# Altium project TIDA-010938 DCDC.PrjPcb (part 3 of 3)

## Sheet TIDA-010938 bidirectional DC-DC_Interleaved2.SchDoc
size 558 x 431 mm; SheetNumber: 8; SheetTotal: 9
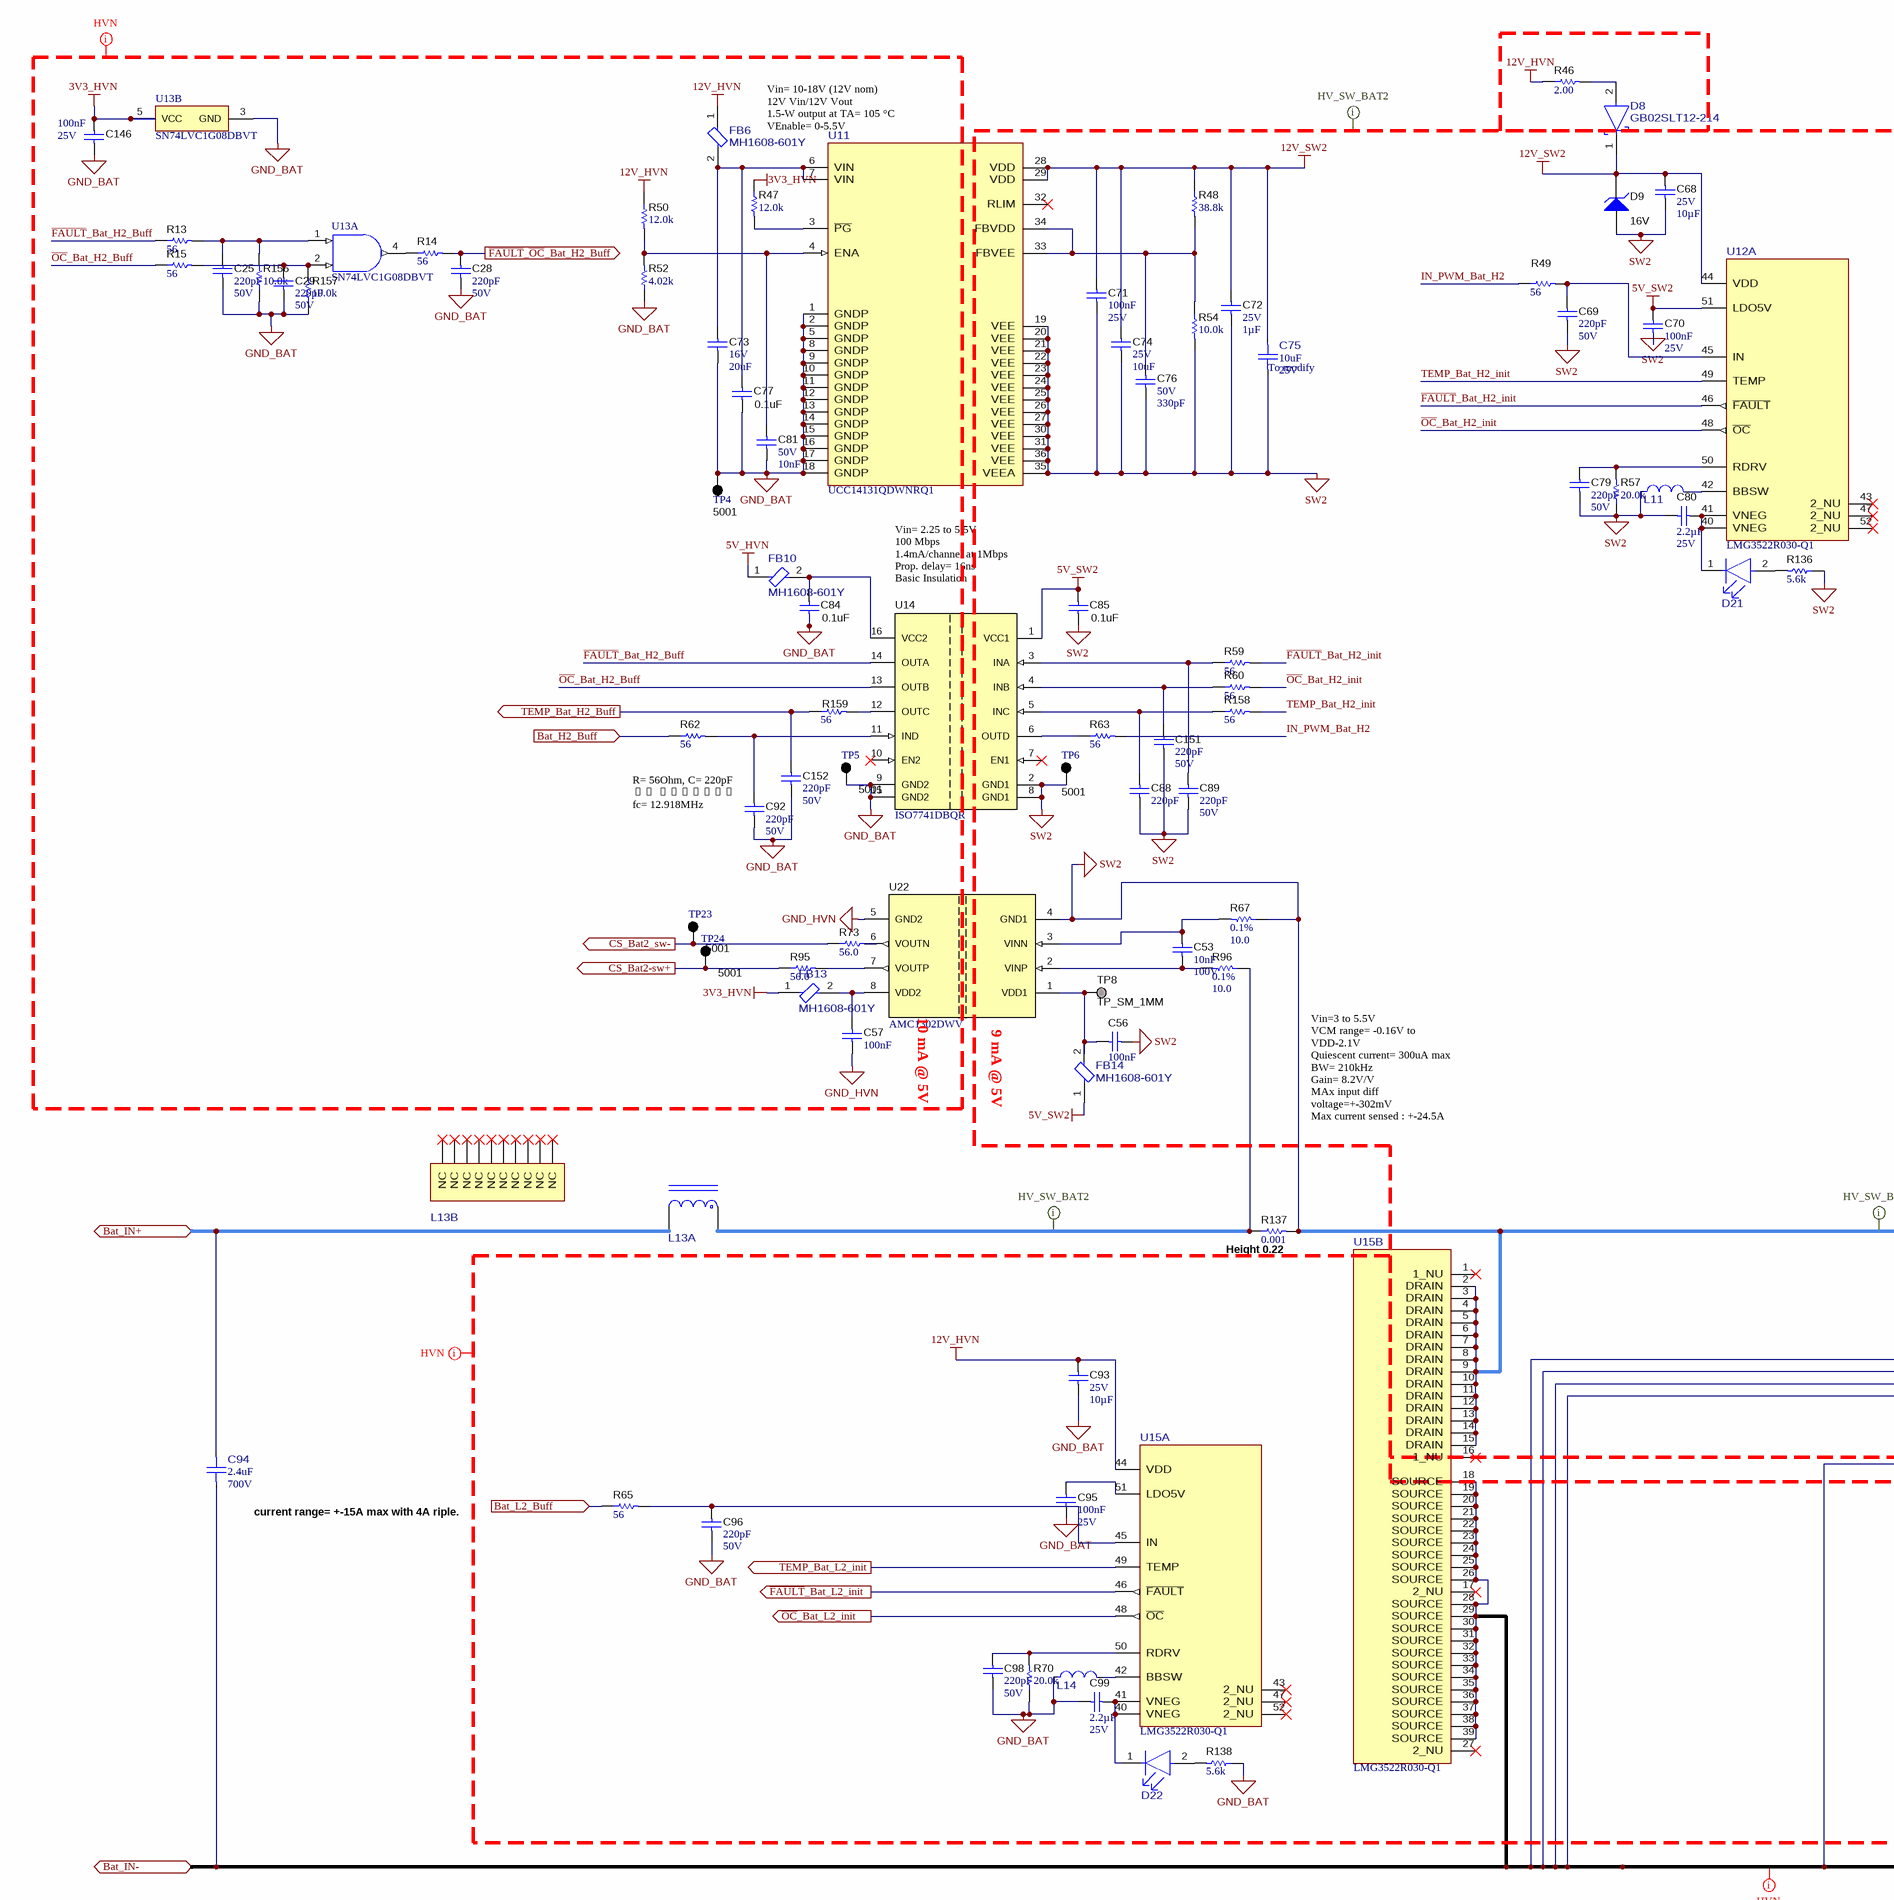
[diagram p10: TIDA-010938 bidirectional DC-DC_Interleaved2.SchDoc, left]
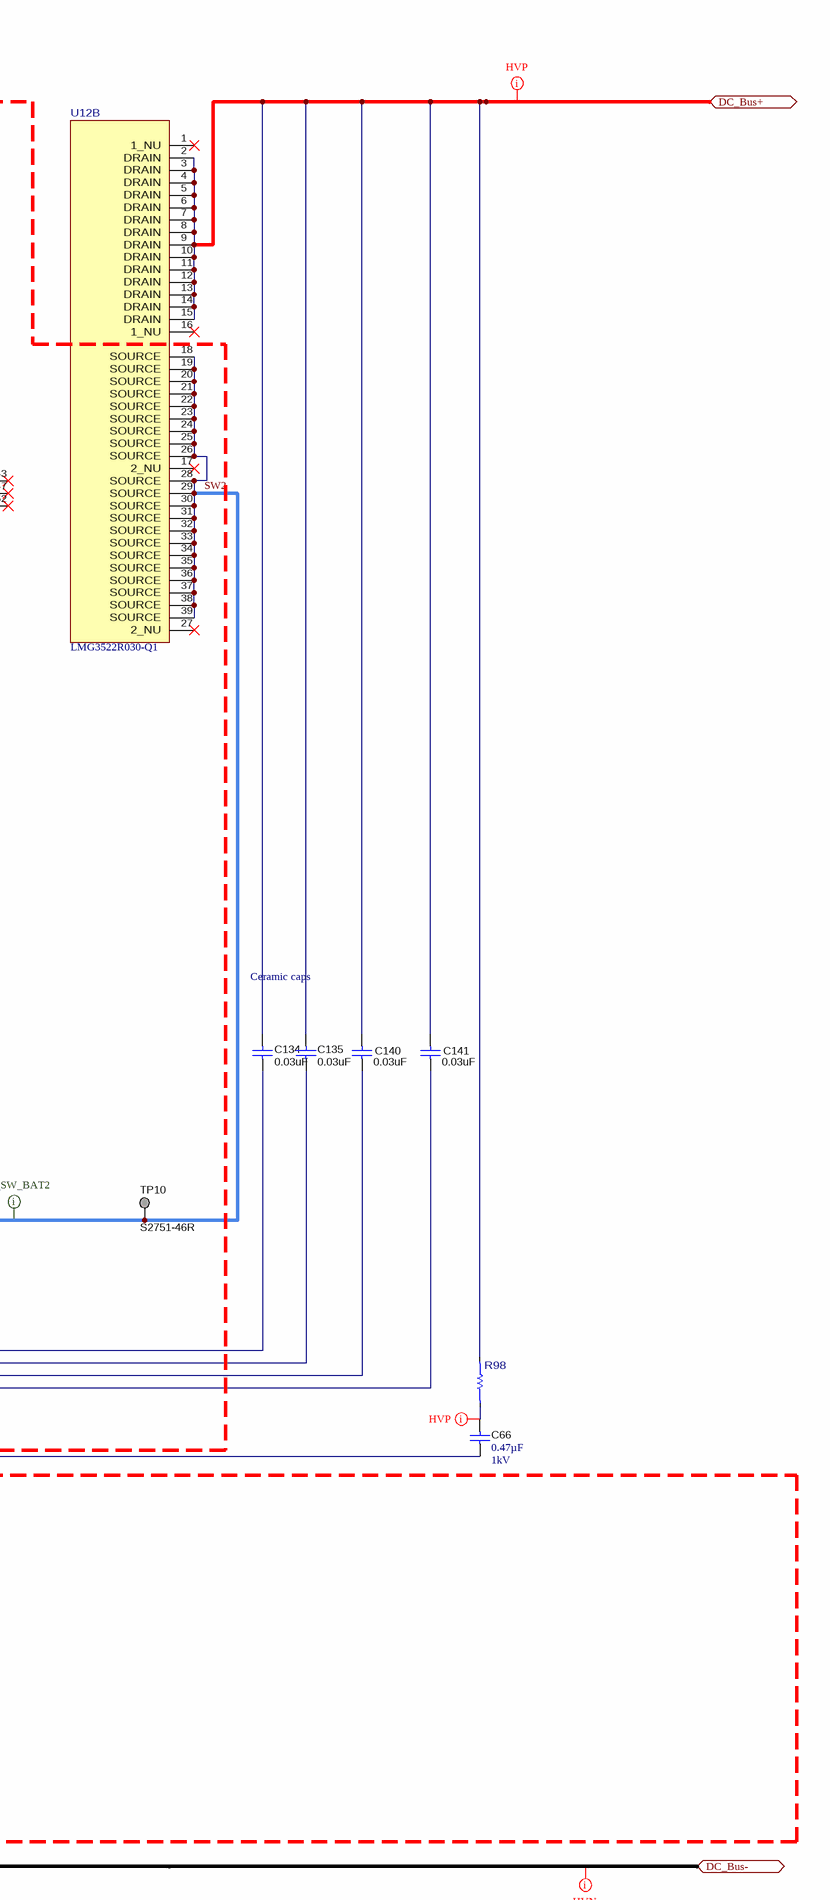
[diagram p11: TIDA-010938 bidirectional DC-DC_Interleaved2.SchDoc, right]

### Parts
C25  Cap_F: 220pF  VDC_V: 50V  [0603]  (hidden comment: GRM188R71H221KA01D)
C28  Cap_F: 220pF  VDC_V: 50V  [0603]  (hidden comment: GRM188R71H221KA01D)
C29  Cap_F: 220pF  VDC_V: 50V  [0603]  (hidden comment: GRM188R71H221KA01D)
C53  Cap_F: 10nF  VDC_V: 100V  [0603]  (hidden comment: CGA3E2X7R2A103K080AA)
C56  Cap_F: 100nF  [0603]  (hidden comment: 06033C104JAT2A)
C57  Cap_F: 100nF  [0603]  (hidden comment: 06033C104JAT2A)
C66  ValueDisplayed: 0.47µF  VDC_V: 1kV  [2220]  (hidden comment: 2220Y1K00474KETWS2)
C68  VDC_V: 25V  ValueDisplayed: 10µF  [1206_180]  (hidden comment: TMK316AB7106KLHT)
C69  Cap_F: 220pF  VDC_V: 50V  [0603]  (hidden comment: GRM188R71H221KA01D)
C70  Cap_F: 100nF  VDC_V: 25V  [0603]  (hidden comment: 06033C104JAT2A)
C71  Cap_F: 100nF  VDC_V: 25V  [0603]  (hidden comment: 06033C104JAT2A)
C72  VDC_V: 25V  ValueDisplayed: 1µF  [0603]  (hidden comment: TMK107BJ105KA-T)
C73  VDC_V: 16V  ValueDisplayed: 20uF  [0704]  (hidden comment: GRMJN7R61C206ME05)
C74  VDC_V: 25V  ValueDisplayed: 10uF  [0603]  (hidden comment: TMK107BBJ106MA-T)
C75  ValueDisplayed: 10uF  VDC_V: 25V  [FP-ZRB18AR61E106ME01L_0603-MFG]  (hidden comment: ZRB18AR61E106ME01L)
C76  VDC_V: 50V  ValueDisplayed: 330pF  [0603]  (hidden comment: GRM1885C1H331JA01D)
C77  ValueDisplayed: 0.1uF  [0603]  (hidden comment: 885012206095)
C79  Cap_F: 220pF  VDC_V: 50V  [0603]  (hidden comment: GRM188R71H221KA01D)
C80  Cap_F: 2.2µF  VDC_V: 25V  [0805_HV]  (hidden comment: CGA4J3X7R1E225K125AB)
C81  VDC_V: 50V  Cap_F: 10nF  [0603]  (hidden comment: 885012206089)
C84  ValueDisplayed: 0.1uF  [0603]  (hidden comment: 885012206095)
C85  ValueDisplayed: 0.1uF  [0603]  (hidden comment: 885012206095)
C88  Cap_F: 220pF  [0603]  (hidden comment: GRM188R71H221KA01D)
C89  Cap_F: 220pF  VDC_V: 50V  [0603]  (hidden comment: GRM188R71H221KA01D)
C92  Cap_F: 220pF  VDC_V: 50V  [0603]  (hidden comment: GRM188R71H221KA01D)
C93  VDC_V: 25V  ValueDisplayed: 10µF  [1206_180]  (hidden comment: TMK316AB7106KLHT)
C94  ValueDisplayed: 2.4uF  VDC_V: 700V  [FP-C4AUJBU4240M1WJ_RADIAL-MFG]  (hidden comment: C4AUJBU4240M1WJ)
C95  Cap_F: 100nF  VDC_V: 25V  [0603]  (hidden comment: 06033C104JAT2A)
C96  Cap_F: 220pF  VDC_V: 50V  [0603]  (hidden comment: GRM188R71H221KA01D)
C98  Cap_F: 220pF  VDC_V: 50V  [0603]  (hidden comment: GRM188R71H221KA01D)
C99  Cap_F: 2.2µF  VDC_V: 25V  [0805_HV]  (hidden comment: CGA4J3X7R1E225K125AB)
C134  ValueDisplayed: 0.03uF  [1812_254]  (hidden comment: C1812C303KDGLCAUTO)
C135  ValueDisplayed: 0.03uF  [1812_254]  (hidden comment: C1812C303KDGLCAUTO)
C140  ValueDisplayed: 0.03uF  [1812_254]  (hidden comment: C1812C303KDGLCAUTO)
C141  ValueDisplayed: 0.03uF  [1812_254]  (hidden comment: C1812C303KDGLCAUTO)
C146  Cap_F: 100nF  VDC_V: 25V  [0603]  (hidden comment: 06033C104JAT2A)
C151  Cap_F: 220pF  VDC_V: 50V  [0603]  (hidden comment: GRM188R71H221KA01D)
C152  Cap_F: 220pF  VDC_V: 50V  [0603]  (hidden comment: GRM188R71H221KA01D)
D8  GB02SLT12-214  [FP-GB02SLT12-214_DO-214AA-MFG]
D9  value 16V  [SOD-123]  (hidden comment: BZT52C16-7-F)
D21  KG DELLS1.22-JGKH-24  [FP-KG DELLS1.22-JGKH-24_0603-MFG]  (value not drawn)
D22  KG DELLS1.22-JGKH-24  [FP-KG DELLS1.22-JGKH-24_0603-MFG]  (value not drawn)
FB6  MH1608-601Y  [FP-MH1608-601Y_0603-MFG]
FB10  MH1608-601Y  [FP-MH1608-601Y_0603-MFG]
FB13  MH1608-601Y  [FP-MH1608-601Y_0603-MFG]
FB14  MH1608-601Y  [FP-MH1608-601Y_0603-MFG]
L11  SDEM20161T-4R7MS  [FP-SDEM20161T-4R7MS_SMD2-MFG]  (value not drawn)
L13  B180975  [FP-B180975_PTH12_55MM5_50MM0-MFG]  (value not drawn)  (parts A,B of 2)
L14  SDEM20161T-4R7MS  [FP-SDEM20161T-4R7MS_SMD2-MFG]  (value not drawn)
R13  ValueDisplayed: 56  [0603]  (hidden comment: RG1608P-560-B-T5)
R14  ValueDisplayed: 56  [0603]  (hidden comment: RG1608P-560-B-T5)
R15  ValueDisplayed: 56  [0603]  (hidden comment: RG1608P-560-B-T5)
R46  ValueDisplayed: 2.00  [0603]  (hidden comment: RT0603DRE072RL)
R47  ValueDisplayed: 12.0k  [0603]  (hidden comment: ERJ-3EKF1202V)
R48  ValueDisplayed: 38.8k  [0603]  (hidden comment: RT0603DRE0738K8L)
R49  ValueDisplayed: 56  [0603]  (hidden comment: RG1608P-560-B-T5)
R50  ValueDisplayed: 12.0k  [0603]  (hidden comment: ERJ-3EKF1202V)
R52  ValueDisplayed: 4.02k  [0603]  (hidden comment: RT0603BRD074K02L)
R54  ValueDisplayed: 10.0k  [0603]  (hidden comment: RG1608P-103-B-T5)
R57  ValueDisplayed: 20.0k  [0603]  (hidden comment: RC0603FR-0720KL)
R59  ValueDisplayed: 56  [0603]  (hidden comment: RG1608P-560-B-T5)
R60  ValueDisplayed: 56  [0603]  (hidden comment: RG1608P-560-B-T5)
R62  ValueDisplayed: 56  [0603]  (hidden comment: RG1608P-560-B-T5)
R63  ValueDisplayed: 56  [0603]  (hidden comment: RG1608P-560-B-T5)
R65  ValueDisplayed: 56  [0603]  (hidden comment: RG1608P-560-B-T5)
R67  Tolerance_%: 0.1%  ValueDisplayed: 10.0  [0603]  (hidden comment: RT0603BRD0710RL)
R70  ValueDisplayed: 20.0k  [0603]  (hidden comment: RC0603FR-0720KL)
R73  ValueDisplayed: 56.0  [0603]  (hidden comment: RC0603FR-0756RL)
R95  ValueDisplayed: 56.0  [0603]  (hidden comment: RC0603FR-0756RL)
R96  Tolerance_%: 0.1%  ValueDisplayed: 10.0  [0603]  (hidden comment: RT0603BRD0710RL)
R98  CSR0805FKR250  [FP-CSR0805FKR250_0805-MFG]  (value not drawn)
R136  ValueDisplayed: 5.6k  [0603]  (hidden comment: RC0603JR-075K6L)
R137  ValueDisplayed: 0.001  [CSS2H-2512_H077Y042]  (hidden comment: CSS2H-2512R-1L00F)
R138  ValueDisplayed: 5.6k  [0603]  (hidden comment: RC0603JR-075K6L)
R156  ValueDisplayed: 10.0k  [0603]  (hidden comment: RG1608P-103-B-T5)
R157  ValueDisplayed: 10.0k  [0603]  (hidden comment: RG1608P-103-B-T5)
R158  ValueDisplayed: 56  [0603]  (hidden comment: RG1608P-560-B-T5)
R159  ValueDisplayed: 56  [0603]  (hidden comment: RG1608P-560-B-T5)
TP4  5001  [Keystone5001]
TP5  5001  [Keystone5001]
TP6  5001  [Keystone5001]
TP8  TP_SM_1MM  [TP_SM_1MM]  (no BOM)
TP10  S2751-46R  [Harwin_S2751-46R]  (no BOM)
TP23  5001  [Keystone5001]
TP24  5001  [Keystone5001]
U11  UCC14131QDWNRQ1  [DWJ0036A-MFG]
U12  LMG3522R030-Q1  [RQS0052C-C01-MFG]  (parts A,B of 2)
U13  SN74LVC1G08DBVT  [DBV0005A_N]  (parts A,B of 2)
U14  ISO7741DBQR  [DBQ0016A_N]
U15  LMG3522R030-Q1  [RQS0052C-C01-MFG]  (parts A,B of 2)
U22  AMC1302DWV  [DWV0008A]

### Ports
Bat_H2_Buff (in), Bat_IN+ (bidir), Bat_IN- (bidir), Bat_L2_Buff (in), CS_Bat2-sw+ (out), CS_Bat2_sw- (out), DC_Bus+ (bidir), DC_Bus- (bidir), TEMP_Bat_H2_Buff (out), TEMP_Bat_L2_init (out), ~{FAULT}_Bat_L2_init (out), ~{FAULT}_~{OC}_Bat_H2_Buff (out), ~{OC}_Bat_L2_init (out)

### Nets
3V3_HVN: C146.1 FB13.1 R47.1 U13.5(VCC)
5V_HVN: FB10.1
5V_SW2: C70.2 C85.1 FB14.1 U12.51(LDO5V) U14.1(VCC1)
12V_HVN: C93.1 FB6.1 R46.1 R50.1 U15.44(VDD)
12V_SW2: C68.1 C71.2 C72.2 C74.2 C75.1 D8.1(CATHODE) D9.1(K) R48.1 U11.28(VDD) U11.29(VDD) U12.44(VDD)
DC_Bus-: C66.2 C94.1 C134.2 C135.2 C140.2 C141.2 U15.18(SOURCE) U15.19(SOURCE) U15.20(SOURCE) U15.21(SOURCE) U15.22(SOURCE) U15.23(SOURCE) U15.24(SOURCE) U15.25(SOURCE) U15.26(SOURCE) U15.28(SOURCE) U15.29(SOURCE) U15.30(SOURCE) U15.31(SOURCE) U15.32(SOURCE) U15.33(SOURCE) U15.34(SOURCE) U15.35(SOURCE) U15.36(SOURCE) U15.37(SOURCE) U15.38(SOURCE) U15.39(SOURCE) ; port DC_Bus-, port Bat_IN-
GND_BAT: C25.1 C28.1 C29.1 C73.1 C77.2 C81.1 C84.2 C92.1 C93.2 C95.1 C96.1 C98.1 C99.2 C146.2 C152.1 L14.1 R52.1 R70.1 R138.1 R156.1 R157.1 TP4.1 TP5.1 U11.1(GNDP) U11.2(GNDP) U11.5(GNDP) U11.8(GNDP) U11.9(GNDP) U11.10(GNDP) U11.11(GNDP) U11.12(GNDP) U11.13(GNDP) U11.14(GNDP) U11.15(GNDP) U11.16(GNDP) U11.17(GNDP) U11.18(GNDP) U13.3(GND) U14.9(GND2) U14.15(GND2)
GND_HVN: C57.2 U22.5(GND2)
SW2: C56.2 C68.2 C69.1 C70.1 C71.1 C72.1 C74.1 C75.2 C76.2 C79.1 C80.2 C85.2 C88.1 C89.1 C151.1 D9.2(A) L11.1 R54.2 R57.1 R67.1 R136.1 R137.2 TP6.1 TP10.1 U11.19(VEE) U11.20(VEE) U11.21(VEE) U11.22(VEE) U11.23(VEE) U11.24(VEE) U11.25(VEE) U11.26(VEE) U11.27(VEE) U11.30(VEE) U11.31(VEE) U11.35(VEEA) U11.36(VEE) U12.18(SOURCE) U12.19(SOURCE) U12.20(SOURCE) U12.21(SOURCE) U12.22(SOURCE) U12.23(SOURCE) U12.24(SOURCE) U12.25(SOURCE) U12.26(SOURCE) U12.28(SOURCE) U12.29(SOURCE) U12.30(SOURCE) U12.31(SOURCE) U12.32(SOURCE) U12.33(SOURCE) U12.34(SOURCE) U12.35(SOURCE) U12.36(SOURCE) U12.37(SOURCE) U12.38(SOURCE) U12.39(SOURCE) U14.2(GND1) U14.8(GND1) U15.2(DRAIN) U15.3(DRAIN) U15.4(DRAIN) U15.5(DRAIN) U15.6(DRAIN) U15.7(DRAIN) U15.8(DRAIN) U15.9(DRAIN) U15.10(DRAIN) U15.11(DRAIN) U15.12(DRAIN) U15.13(DRAIN) U15.14(DRAIN) U15.15(DRAIN) U22.4(GND1)
Bat_H2_Buff: R62.1 ; port Bat_H2_Buff
Bat_IN+: C94.2 L13.6 ; port Bat_IN+
Bat_L2_Buff: R65.1 ; port Bat_L2_Buff
CS_Bat2-sw+: R95.1 TP24.1 ; port CS_Bat2-sw+
CS_Bat2_sw-: R73.1 TP23.1 ; port CS_Bat2_sw-
DC_Bus+: C134.1 C135.1 C140.1 C141.1 R98.2 U12.2(DRAIN) U12.3(DRAIN) U12.4(DRAIN) U12.5(DRAIN) U12.6(DRAIN) U12.7(DRAIN) U12.8(DRAIN) U12.9(DRAIN) U12.10(DRAIN) U12.11(DRAIN) U12.12(DRAIN) U12.13(DRAIN) U12.14(DRAIN) U12.15(DRAIN) ; port DC_Bus+
~{FAULT}_Bat_H2_Buff: R13.1 U14.14(OUTA)
~{FAULT}_Bat_H2_init: R59.2 U12.46(~{FAULT})
~{FAULT}_Bat_L2_init: U15.46(~{FAULT}) ; port ~{FAULT}_Bat_L2_init
~{FAULT}_~{OC}_Bat_H2_Buff: C28.2 R14.2 ; port ~{FAULT}_~{OC}_Bat_H2_Buff
IN_PWM_Bat_H2: R49.1 R63.2
~{OC}_Bat_H2_Buff: R15.1 U14.13(OUTB)
~{OC}_Bat_H2_init: R60.2 U12.48(~{OC})
~{OC}_Bat_L2_init: U15.48(~{OC}) ; port ~{OC}_Bat_L2_init
TEMP_Bat_H2_Buff: C152.2 R159.1 ; port TEMP_Bat_H2_Buff
TEMP_Bat_H2_init: R158.2 U12.49(TEMP)
TEMP_Bat_L2_init: U15.49(TEMP) ; port TEMP_Bat_L2_init
NetC25_2: C25.2 R13.2 R156.2 U13.1(A)
NetC29_2: C29.2 R15.2 R157.2 U13.2(B)
NetC53_1: C53.1 R96.2 U22.2(VINP)
NetC53_2: C53.2 R67.2 U22.3(VINN)
NetC56_1: C56.1 FB14.2 TP8.1 U22.1(VDD1)
NetC57_1: C57.1 FB13.2 U22.8(VDD2)
NetC66_1: C66.1 R98.1
NetC69_2: C69.2 R49.2 U12.45(IN)
NetC73_2: C73.2 C77.1 FB6.2 U11.6(VIN) U11.7(VIN)
NetC76_1: C76.1 R48.2 R54.1 U11.33(FBVEE) U11.34(FBVDD)
NetC79_2: C79.2 R57.2 U12.50(RDRV)
NetC80_1: C80.1 D21.1(CATHODE) U12.40(VNEG) U12.41(VNEG)
NetC81_2: C81.2 R50.2 R52.2 U11.4(ENA)
NetC84_1: C84.1 FB10.2 U14.16(VCC2)
NetC88_2: C88.2 R158.1 U14.5(INC)
NetC89_2: C89.2 R59.1 U14.3(INA)
NetC92_2: C92.2 R62.2 U14.11(IND)
NetC95_2: C95.2 U15.51(LDO5V)
NetC96_2: C96.2 R65.2 U15.45(IN)
NetC98_2: C98.2 R70.2 U15.50(RDRV)
NetC99_1: C99.1 D22.1(CATHODE) U15.40(VNEG) U15.41(VNEG)
NetC151_2: C151.2 R60.1 U14.4(INB)
NetD8_2: D8.2(ANODE) R46.2
NetD21_2: D21.2(ANODE) R136.2
NetD22_2: D22.2(ANODE) R138.2
NetL11_2: L11.2 U12.42(BBSW)
NetL13_1: L13.1 R96.1 R137.1
NetL14_2: L14.2 U15.42(BBSW)
NetR14_1: R14.1 U13.4(Y)
NetR47_2: R47.2 U11.3(~{PG})
NetR63_1: R63.1 U14.6(OUTD)
NetR73_2: R73.2 U22.6(VOUTN)
NetR95_2: R95.2 U22.7(VOUTP)
NetR159_2: R159.2 U14.12(OUTC)

Not connected (* = marked no-connect by the designer): L13 2(NC)* 3(NC)* 4(NC)* 5(NC)* 7(NC)* 8(NC)* 9(NC)* 10(NC)* 11(NC)* 12(NC)*; U11 32(RLIM)*; U12 1(1_NU)* 16(1_NU)* 17(2_NU)* 27(2_NU)* 43(2_NU)* 47(2_NU)* 52(2_NU)*; U14 7(EN1)* 10(EN2)*; U15 1(1_NU)* 16(1_NU)* 17(2_NU)* 27(2_NU)* 43(2_NU)* 47(2_NU)* 52(2_NU)*

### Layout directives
net class HVN: 3V3_HVN, 5V_HVN, 12V_HVN, DC_Bus-, GND_BAT, GND_HVN, ~{FAULT}_Bat_H2_Buff, ~{OC}_Bat_H2_Buff
net class HV_SW_BAT2: 5V_SW2, 12V_SW2, GND_BAT, IN_PWM_Bat_H2, NetL13_1, SW2, TEMP_Bat_H2_init, ~{FAULT}_Bat_H2_init, ~{OC}_Bat_H2_init
net class HVP: DC_Bus+, NetC66_1

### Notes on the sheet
- Vin= 10-18V (12V nom)
  12V Vin/12V Vout
  1.5-W output at TA= 105 °C
  VEnable= 0-5.5V
- (near C75) To modify
- Vin= 2.25 to 5.5V
  100 Mbps
  1.4mA/channel at 1Mbps
  Prop. delay= 16ns
  Basic Insulation
- (near C92) R= 56Ohm, C= 220pF
  𝜏= 1.23e-8
  fc= 12.918MHz
- (near U22) 10 mA @ 5V
- Ceramic caps
- (near U22) 9 mA @ 5V
- Vin=3 to 5.5V
  VCM range= -0.16V to VDD-2.1V
  Quiescent current= 300uA max
  BW= 210kHz
  Gain= 8.2V/V
  MAx input diff voltage=+-302mV
  Max current sensed : +-24.5A
- (near R137) Height 0.22
- (near C94) current range= +-15A max with 4A riple.

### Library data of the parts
C25 C28 C29 C69 C79 C89 C92 C96 C98 C151 C152 = CMP-0007442-5: CAP, CERM, 220 pF, 50 V, +/- 10%, X7R, 0603; Manufacturer: MuRata; TaMin_C: -55°C; Polarized: N; SizeAreaWB_mm2: 4.68; Value1: Unknown; U/M: EA; Value: 220pF; TaMax_C: 125°C; SizeZ_mm: 1; SizeX_mm: 1.6; SizeY_mm: 0.8; SizeArea_mm2: 1.28; AEC Category: Q200
C53 = CMP-0007082-4: CAP, CERM, 0.01 uF, 100 V, +/- 10%, X7R, AEC-Q200 Grade 1, 0603; Manufacturer: TDK; TaMin_C: -55°C; ESR_ohm: 2.35428d; Polarized: N; SizeAreaWB_mm2: 4.68; Value1: 0.235428 ohm; U/M: EA; Value: 0.01uF; TaMax_C: 125°C; SizeZ_mm: 1; SizeX_mm: 1.6; SizeY_mm: 0.8; SizeArea_mm2: 1.28; AEC Qualified: Y; IRMS_A: 3.96995dA; AEC Category: Q200
C56 C57 = CMP-0006752-5: CAP, CERM, 0.1 uF, 25 V, +/- 5%, X7R, 0603; Manufacturer: AVX; TaMin_C: -55°C; ESR_ohm: 0.05; Polarized: N; SizeAreaWB_mm2: 4.68; Value1: 0.05 ohm; U/M: EA; Value: 0.1uF; TaMax_C: 125°C; SizeZ_mm: 1; SizeX_mm: 1.6; SizeY_mm: 0.8; Value2: 25V; SizeArea_mm2: 1.28; AEC Category: Q200
C66 = CMP-0086177-1: CAP, CERM, 0.47 µF, 1000 V,+/- 10%, X7R, AEC-Q200 Grade 1, 2220; Manufacturer: Knowles Capacitors; SizeAreaWB_mm2: 53.9; AEC Category: Q200; TaMax_C: 125°C; SizeArea_mm2: 28.5; SizeX_mm: 5.7; SizeZ_mm: 1.35; Value: 0.47uF; AEC Qualified: Y; TaMin_C: -55°C; SizeY_mm: 5; Value2: 1000V; AEC Grade: 1; U/M: EA; Cap_F: 470nF; Polarized: N
C68 C93 = CMP-0750154-1: CAP, CERM, 10 µF, 25 V,+/- 10%, X7R, AEC-Q200 Grade 1, 1206; Manufacturer: Taiyo Yuden; AEC Qualified: Y; SizeZ_mm: 1.8; TaMax_C: 125°C; TaMin_C: -55°C; Cap_Case: 1206; Polarized: N; AEC Grade: 1; SizeY_mm: 1.6; Value: 10uF; SizeX_mm: 3.2; SizeAreaWB_mm2: 10.92; AEC Category: Q200; U/M: EA; SizeArea_mm2: 5.12
C70 C71 C95 C146 = CMP-0006752-5: CAP, CERM, 0.1 uF, 25 V, +/- 5%, X7R, 0603; Manufacturer: AVX; TaMin_C: -55°C; ESR_ohm: 0.05; Polarized: N; SizeAreaWB_mm2: 4.68; Value1: 0.05 ohm; U/M: EA; Value: 0.1uF; TaMax_C: 125°C; SizeZ_mm: 1; SizeX_mm: 1.6; SizeY_mm: 0.8; SizeArea_mm2: 1.28; AEC Category: Q200
C72 = CMP-0086152-1: CAP, CERM, 1 µF, 25 V,+/- 10%, X5R, 0603; Manufacturer: Taiyo Yuden; SizeAreaWB_mm2: 4.68; SizeZ_mm: 1; U/M: EA; Green_REACh: Passed; Value: 1uF; AEC Qualified: N; TaMax_C: 85°C; Green_Lifecycle: Active; AEC Category: Q200; SizeArea_mm2: 1.28; TaMin_C: -55°C; SizeY_mm: 0.8; SizeX_mm: 1.6
C73 = CMP-0009474-2: CAP, CERM, 20 uF, 16 V, +/- 20%, X5R, 0704; Manufacturer: MuRata; TaMin_C: -55°C; Polarized: N; SizeAreaWB_mm2: 5.6; Value1: Unknown; U/M: EA; Value: 20uF; TaMax_C: 85°C; SizeZ_mm: 0.8; SizeX_mm: 1; SizeY_mm: 1.8; Cap_F: 20µF; AEC Category: Q200
C74 = CMP-0007507-5: CAP, CERM, 10 uF, 25 V, +/- 20%, X5R, 0603; Manufacturer: Taiyo Yuden; TaMin_C: -55°C; Polarized: N; SizeAreaWB_mm2: 4.68; Value1: Unknown; U/M: EA; Value: 10uF; TaMax_C: 85°C; SizeZ_mm: 1; SizeX_mm: 1.6; SizeY_mm: 0.8; SizeArea_mm2: 1.28; Cap_F: 10µF; AEC Category: Q200
C75 = CMP-0094458-1: 10µF ±20% 25V Ceramic Capacitor X5R 0603 (1608 Metric); Manufacturer: Murata Electronics; SizeZ_mm: 1.2mm; AEC Qualified: No
C76 = CMP-0007209-4: CAP, CERM, 330 pF, 50 V, +/- 5%, C0G/NP0, 0603; Manufacturer: MuRata; TaMin_C: -55°C; Polarized: N; SizeAreaWB_mm2: 4.68; Value1: Unknown; U/M: EA; Value: 330pF; TaMax_C: 125°C; SizeZ_mm: 1; SizeX_mm: 1.6; SizeY_mm: 0.8; SizeArea_mm2: 1.28; AEC Category: Q200
C77 C84 C85 = CMP-0006837-4: CAP, CERM, 0.1 uF, 50 V, +/- 10%, X7R, 0603; Manufacturer: Wurth Elektronik; TaMin_C: -55°C; Polarized: N; SizeAreaWB_mm2: 4.68; Value1: Unknown; U/M: EA; Value: 0.1uF; TaMax_C: 125°C; SizeZ_mm: 1; SizeX_mm: 1.6; SizeY_mm: 0.8; Value2: 50V; SizeArea_mm2: 1.28; CompType: Capacitor; Cap_F: 100nF; AEC Category: Q200
C80 C99 = CMP-0007975-2: CAP, CERM, 2.2 uF, 25 V, +/- 10%, X7R, AEC-Q200 Grade 1, 0805; Manufacturer: TDK; TaMin_C: -55°C; Polarized: N; SizeAreaWB_mm2: 6.75; Value1: Unknown; U/M: EA; Value: 2.2uF; TaMax_C: 125°C; SizeZ_mm: 1.45; SizeX_mm: 2; SizeY_mm: 1.25; Cap_Case: 0805; SizeArea_mm2: 2.5; AEC Qualified: Y; AEC Grade: 1; AEC Category: Q200
C81 = CMP-0750039-1: CAP, CERM, 0.01 µF, 50 V,+/- 10%, X7R, 0603; Manufacturer: Wurth Elektronik; Polarized: N; AEC Category: Q200; TaMax_C: 125°C; SizeAreaWB_mm2: 4.68; Value: 0.01uF; SizeArea_mm2: 1.28; SizeY_mm: 0.8; SizeZ_mm: 1; ValueDisplayed: 0.01µF; SizeX_mm: 1.6; U/M: EA; TaMin_C: -55°C
C88 = CMP-0007442-5: CAP, CERM, 220 pF, 50 V, +/- 10%, X7R, 0603; Manufacturer: MuRata; TaMin_C: -55°C; Polarized: N; SizeAreaWB_mm2: 4.68; Value1: Unknown; U/M: EA; Value: 220pF; TaMax_C: 125°C; SizeZ_mm: 1; SizeX_mm: 1.6; SizeY_mm: 0.8; Value2: 50V; SizeArea_mm2: 1.28; AEC Category: Q200
C94 = CMP-0045063-1: 2.4 µF Film Capacitor 700V Polypropylene (PP), Metallized Radial; Manufacturer: KEMET; AEC Grade: Grade 2; AEC Qualified: Yes; Cap_F: 2.4µF; SizeZ_mm: 20.7mm; Tolerance_%: 5%; Value: 2.4µF
C134 C135 C140 C141 = CMP-0009326-2: 0.03 µF ±10% 1000V (1kV) Ceramic Capacitor C0G, NP0 1812 (4532 Metric); Manufacturer: Kemet; Polarized: N; Value: 0.03uF; U/M: EA; Cap_F: 30nF; Value1: Unknown; TaMin_C: -55°C; TaMax_C: 125°C; Cap_Case: 1812; AEC Category: Q200; SizeArea_mm2: 14.4; SizeAreaWB_mm2: 23.1; SizeX_mm: 4.5; SizeY_mm: 3.2; SizeZ_mm: 2.54
D8 = CMP-0095009-1: Diode Silicon Carbide Schottky 1200 V 2A (DC) Surface Mount DO-214AA; Manufacturer: GeneSiC Semiconductor; Max Surge Forward Current: 20A; ValueDisplayed: 122pF; Vf_V: 1.2kV; Peak Reverse Current: 1uA; SizeZ_mm: 2.44mm; AEC Qualified: No; TJmax_C: 175°C
D9 = CMP-0005769-4: Diode, Zener, 16 V, 500 mW, AEC-Q101, SOD-123; Manufacturer: Diodes Inc.; SizeZ_mm: 1.35; AEC Qualified: Y; SizeX_mm: 3.85; AEC Category: Q101; Power_W: 500mW; SizeY_mm: 1.7; Value1: 0.5W; SizeAreaWB_mm2: 13.095; SizeArea_mm2: 6.545; RJA_CperW: 338
D21 D22 = CMP-0093310-1: Standard LEDs - SMD Green TOPLED E 1608; Manufacturer: Osram Opto; AEC Grade: Grade 2; LambdaP: 572nm; SizeZ_mm: 0.7mm; LuminousFlux_PhiV: 0.016-0.0295lm; Luminous Intensity: 4.5-9.7mcd; LambdaD: 570nm; Tjmax_C: 125°C; Angle: 120°; Led Orientation: Top View; Forward Current: 2mA; Vf_V: 1.8V; AEC Qualified: Yes; Vr_V: 12V
FB6 FB10 FB13 FB14 = CMP-0037505-1: 600 Ohms @ 100 MHz 1 Power, Signal Line Ferrite Bead 0603 (1608 Metric) 1A 200mOhm; Manufacturer: Bourns; DCR_ohm: 0.2; SizeZ_mm: 1mm; AEC Qualified: No; Impedance At Frequency: 600Ω @ 100MHz; Test Frequency: 100MHz; Tolerance_%: 25%
L11 L14 = CMP-0089347-1: 4.7µH Unshielded Inductor 1.1A 426mOhm Max 0806 (2016 Metric); Manufacturer: Cyntec; AEC Qualified: No; Material: Metal Dust; Isat: 1.26A; Test Frequency: 1MHz; DCR_ohm: 0.426; SizeZ_mm: 1mm; Tolerance_%: 20%
L13 = CMP-0048784-1: Bi-directional DC-DC Inductor 186.7µH ± 10%; Manufacturer: Bourns; AEC Qualified: No; SizeZ_mm: 45mm; Value: 186.7uH; Test Frequency: 100kHz
R13-R15 R49 R59 R60 R62 R63 R65 R158 R159 = CMP-0023572-3: RES, 56, 0.1%, 0.1 W, 0603; Manufacturer: Susumu Co Ltd; Power_W: 100mW; TempCo: 25 ppm/C; Value_Code: 56R0; U/M: EA; Value: 56; SizeX_mm: 1.6; SizeY_mm: 0.8; SizeZ_mm: 1; Value2: 0.1W; SizeArea_mm2: 1.28; VDC_V: 75V; AEC Category: Q200
R46 = CMP-0025114-2: RES, 2.00, 0.5%, 0.1 W, 0603; Manufacturer: Yageo America; Power_W: 100mW; TempCo: 50 ppm/C; Value_Code: 2R00; U/M: EA; Value: 2.00; EIA_Code: E192; Res_ohm: 2; SizeX_mm: 1.6; SizeY_mm: 0.8; SizeZ_mm: 1; Value2: 0.1W; SizeArea_mm2: 1.28; VDC_V: 75V; AEC Category: Q200
R47 R50 = CMP-0022685-3: RES, 12.0 k, 1%, 0.1 W, 0603; Manufacturer: Panasonic; Power_W: 100mW; TempCo: 100 ppm/C; Value_Code: 12k0; U/M: EA; Value: 12.0k; Res_ohm: 12k; SizeX_mm: 1.6; SizeY_mm: 0.8; SizeZ_mm: 1; Value2: 0.1W; SizeArea_mm2: 1.28; VDC_V: 75V; AEC Category: Q200
R48 = CMP-0025200-2: RES, 38.8 k, 0.5%, 0.1 W, 0603; Manufacturer: Yageo America; Power_W: 100mW; TempCo: 50 ppm/C; Value_Code: 38k8; U/M: EA; Value: 38.8k; EIA_Code: E192; SizeX_mm: 1.6; SizeY_mm: 0.8; SizeZ_mm: 1; Value2: 0.1W; SizeArea_mm2: 1.28; VDC_V: 75V; AEC Category: Q200
R52 = CMP-0024286-2: RES, 4.02 k, 0.1%, 0.1 W, 0603; Manufacturer: Yageo America; Power_W: 100mW; TempCo: 25 ppm/C; Value_Code: 4k02; U/M: EA; Value: 4.02k; EIA_Code: E192; SizeX_mm: 1.6; SizeY_mm: 0.8; SizeZ_mm: 1; Value2: 0.1W; SizeArea_mm2: 1.28; VDC_V: 75V; AEC Category: Q200
R54 = CMP-0023404-1: RES, 10.0 k, 0.1%, 0.1 W, 0603; Manufacturer: Susumu Co Ltd; Power_W: 100mW; TempCo: 25 ppm/C; Value_Code: 10k0; U/M: EA; Value: 10.0k; EIA_Code: E192; Res_ohm: 10k; SizeX_mm: 1.6; SizeY_mm: 0.8; SizeZ_mm: 1; Value2: 0.1W; SizeArea_mm2: 1.28; VDC_V: 75V; AEC Category: Q200
R57 R70 = CMP-0022906-5: RES, 20.0 k, 1%, 0.1 W, 0603; Manufacturer: Yageo; Power_W: 100mW; TempCo: 100 ppm/C; Value_Code: 20k0; Value: 20.0k; EIA_Code: E96; Res_ohm: 20k; SizeX_mm: 1.6; SizeY_mm: 0.8; SizeZ_mm: 1; Value2: 0.1W; SizeArea_mm2: 1.28; AEC Qualified: N; VDC_V: 75V; AEC Category: Q200; SizeAreaWB_mm2: 4.68
R67 R96 = CMP-0023661-3: RES, 10.0, 0.1%, 0.1 W, 0603; Manufacturer: Yageo America; Power_W: 100mW; TempCo: 25 ppm/C; Value_Code: 10R0; U/M: EA; Value: 10.0; EIA_Code: E192; Res_ohm: 10; SizeX_mm: 1.6; SizeY_mm: 0.8; SizeZ_mm: 1; Value2: 0.1W; SizeArea_mm2: 1.28; VDC_V: 75V; AEC Category: Q200
R73 R95 = CMP-0023188-5: RES, 56.0, 1%, 0.1 W, 0603; Manufacturer: Yageo; Power_W: 100mW; TempCo: 100 ppm/C; Value_Code: 56R0; Value: 56.0; Res_ohm: 56; SizeX_mm: 1.6; SizeY_mm: 0.8; SizeZ_mm: 1; Value2: 0.1W; SizeArea_mm2: 1.28; AEC Qualified: N; VDC_V: 75V; AEC Category: Q200; SizeAreaWB_mm2: 4.68
R98 = CMP-0088568-2: 250 mOhms ±1% 0.25W, 1/4W Chip Resistor 0805 (2012 Metric) Current Sense Thick Film; Manufacturer: Stackpole Electronics Inc; TempCo: 200ppm/°C; Res_ohm: 0.25; Power_W: 250mW; SizeZ_mm: 0.65mm; AEC Qualified: No
R136 R138 = CMP-0025933-5: RES, 5.6 k, 5%, 0.1 W, 0603; Manufacturer: Yageo; Power_W: 100mW; TempCo: 100 ppm/C; Value_Code: 5k60; Value: 5.6k; EIA_Code: E24; SizeX_mm: 1.6; SizeY_mm: 0.8; SizeZ_mm: 1; Value2: 0.1W; SizeArea_mm2: 1.28; AEC Qualified: N; VDC_V: 75V; AEC Category: Q200; SizeAreaWB_mm2: 4.68
R137 = CMP-0084746-1: RES, 0.001, 1%, 5 W, AEC-Q200 Grade 0, 6.35x3.05mm; Manufacturer: Bourns; SizeAreaWB_mm2: 42.1675; SizeArea_mm2: 19.3675; SizeY_mm: 3.05; SizeX_mm: 6.35; AEC Grade: 0; EIA_Code: E96; Value: 0.001; Res_ohm: 1m; Power_W: 5W; SizeZ_mm: 0.87; TempCo: 75 ppm/C; Value_Code: 1L000; AEC Qualified: Y; AEC Category: Q200
R156 R157 = CMP-0023404-3: RES, 10.0 k, 0.1%, 0.1 W, 0603; Manufacturer: Susumu Co Ltd; Power_W: 100mW; TempCo: 25 ppm/C; Value_Code: 10k0; U/M: EA; Value: 10.0k; EIA_Code: E192; Res_ohm: 10k; SizeX_mm: 1.6; SizeY_mm: 0.8; SizeZ_mm: 1; Value2: 0.1W; SizeArea_mm2: 1.28; VDC_V: 75V; AEC Category: Q200
TP4-TP6 TP23 TP24 = CMP-0055138-2: Test Point, Miniature, Black, TH; Manufacturer: Keystone Electronics; ContactFinish: Silver; CNHeader: FALSE; Green_Lifecycle: Active; Green_REACh: Passed; CT: TRUE
TP8 = CMP-0003825-1: 1mm Test Point, SMT; Manufacturer: Any
TP10 = CMP-0003968-1: Test Point, SMT; Manufacturer: Harwin
U11 = CMP-0033793-2: Automotive 1.5-W, 12-V VIN / 12-VOUT, 15-V VIN / 15-V VOUT, HighDensity, > 5-kVRMS, Isolated DC/DC Module; Manufacturer: Texas Instruments; SizeZ_mm: 3.55mm; AEC Qualified: Yes; AEC Grade: Grade 1; Max Supply Voltage: 18V; Min Supply Voltage: 9V; Nominal Supply Current: 200-270mA; Number Of Outputs: 2; Output Type: AdjustableProgrammable; Output Voltage: 10-18V; Standoff Height: 0.1mm; Switching Frequency: 18MHz; TaMax_C: +125°C; TaMin_C: -40°C; TJmax_C: +150°C; AEC Category: Q200; CompType: IC
U12 U15 = CMP-0094891-1: 650-V 30-mΩ GaN FET with Integrated Driver, Protection, and Temperature Reporting; Manufacturer: Texas Instruments; Max Supply Voltage: 18V; TaMax_C: +125°C; TaMin_C: -40°C; Nominal Supply Current: 16mA; Number Of Outputs: 1; Standoff Height: 0mm; Min Supply Voltage: 7.5V; TJmax_C: +150°C; AEC Grade: Grade 1; SizeZ_mm: 1mm; Output Voltage: 520V; AEC Qualified: Yes
U13 = CMP-0051571-2: Single 2-Input Positive-AND Gate, DBV0005A, SMALL T&R; Manufacturer: Texas Instruments; Voltage(Nom)(V): 1.8,2.5,3.3,5; Bits(#): 1; Rating: Catalog; F @ Nom Voltage(Max)(Mhz): 150; 3-State Output: No; Gate Type: AND; Output Drive (IOL/IOH)(Max)(mA): 32/-32; Technology Family: LVC; Logic: True; VCC(Max)(V): 5.5; ICC @ Nom Voltage(Max)(mA): 0.01; VCC(Min)(V): 1.65; tpd @ Nom Voltage(Max)(ns): 4.5,6,4,5; Input Type: CMOS/TTL; Output Type: CMOS; AEC Category: Q200; AEC Qualified: N; CompType: IC
U14 = CMP-0013040-3: High Speed, Robust EMC Quad-Channel Digital Isolators, DBQ0016A (SSOP-16); Manufacturer: Texas Instruments; SizeX_mm: 6; SizeY_mm: 10; CompType: IC; SizeZ_mm: 1.75; SizeArea_mm2: 60; SizeAreaWB_mm2: 96; AEC Category: Q200; AEC Qualified: N
U22 = CMP-0080671-1: Precision Reinforced Isolated Amplifier for Current Sensing, DWV0008A (SOIC-8); Alternate PartNumber: AMC1302DWVR; Alternate Manufacturer: Texas Instruments; SizeAreaWB_mm2: 105.975; SizeZ_mm: 2.8; SizeX_mm: 11.5; SizeY_mm: 5.85; SizeArea_mm2: 67.275; CompType: IC; AEC Qualified: N; AEC Category: Q200

## Sheet TIDA-010938 DCDC_Hardware.SchDoc
size 431 x 279 mm; Date: Not shown in title block; ApprovedBy: Not shown in title block; CheckedBy: Not shown in title block; Author: Not shown in title block; CompanyName: Not shown in title block; Engineer: Not shown in title block; Organization: Not shown in title block; Address1: Not shown in title block; Address2: Not shown in title block; Address3: Not shown in title block; Address4: Not shown in title block; DocumentNumber: 3; Revision: Use project parameter SCH_Rev; SheetNumber: 8; SheetTotal: 8; PageSetup: Record=PageOptions¦CenterHorizontal=True¦CenterVertical=True¦PrintScale=1.00¦XCorrection=1.00¦YCorrection=1.00¦PrintKind=0¦BorderSize=5000000¦LeftOffset=0¦BottomOffset=0¦Orientation=2¦PaperLength=1000¦PaperWidth=1000¦Scale=100¦PaperSource=15¦PrintQuality=600¦MediaType=1¦DitherType=10¦PaperKind=Letter¦PrintScaleMode=1
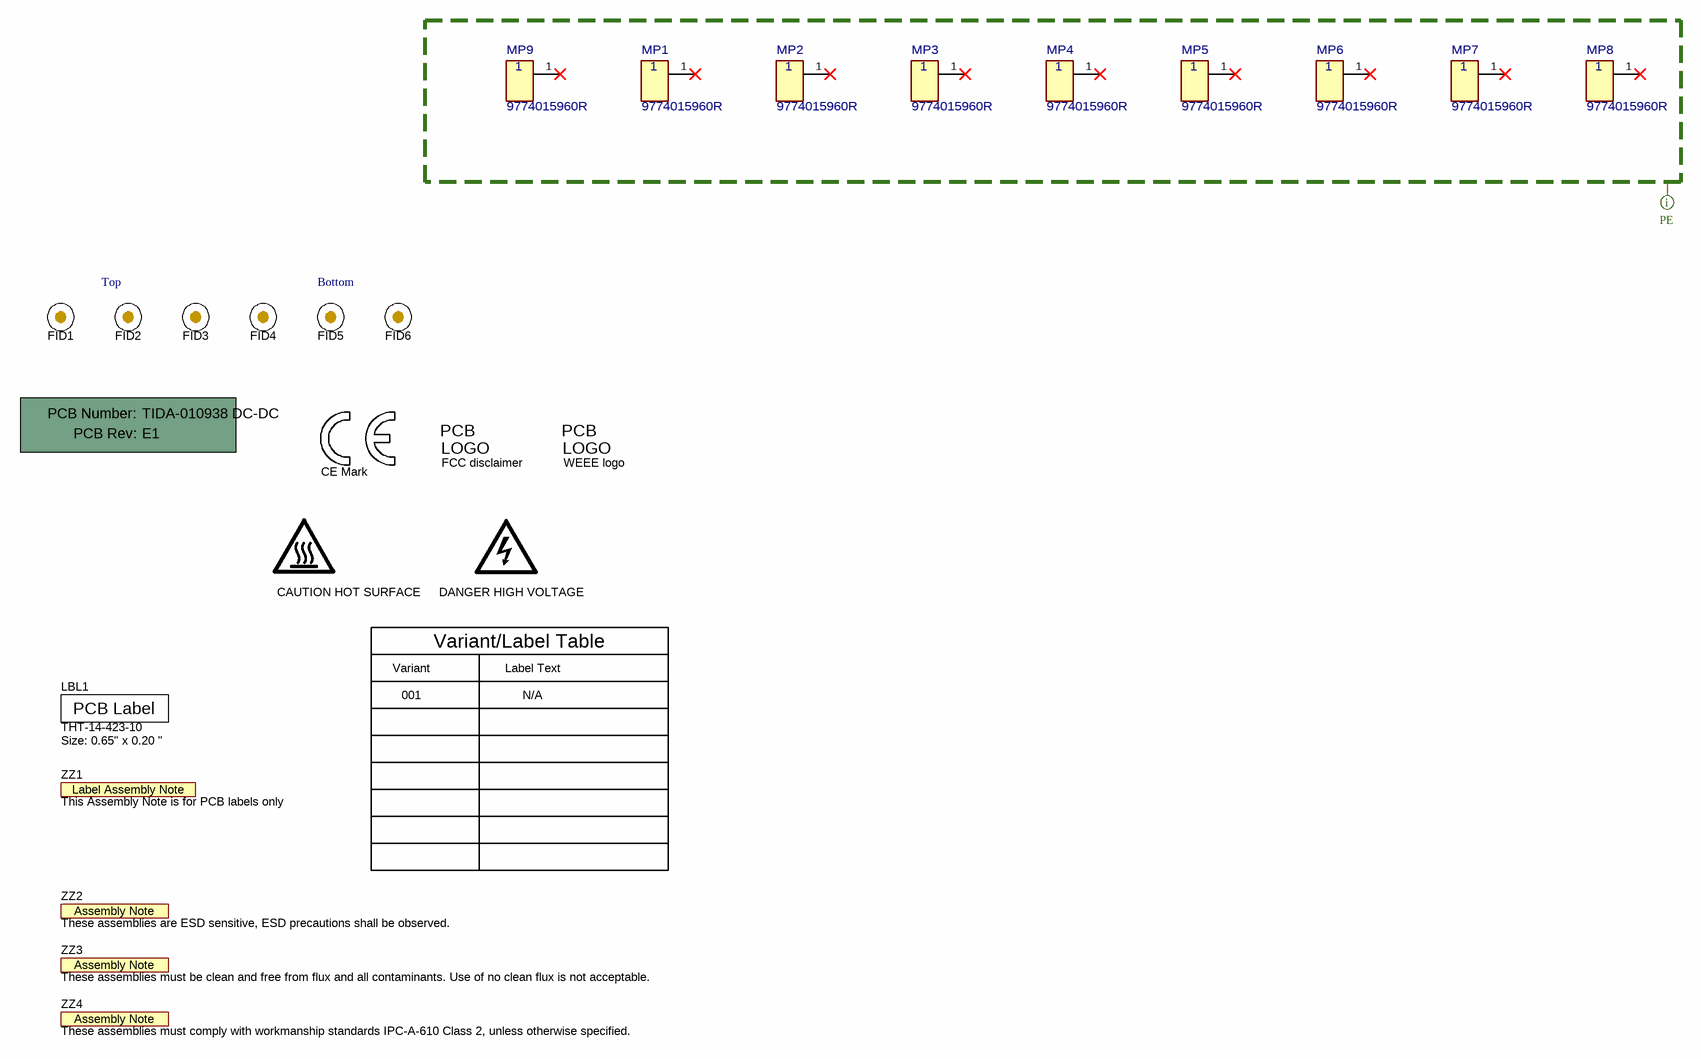
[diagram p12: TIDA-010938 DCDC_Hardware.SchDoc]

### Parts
!PCB  Printed Circuit Board  (value not drawn)  (mechanical)
FID1  Fiducial  [Fiducial10-20]  (value not drawn)
FID2  Fiducial  [Fiducial10-20]  (value not drawn)
FID3  Fiducial  [Fiducial10-20]  (value not drawn)
FID4  Fiducial  [Fiducial10-20]  (value not drawn)
FID5  Fiducial  [Fiducial10-20]  (value not drawn)
FID6  Fiducial  [Fiducial10-20]  (value not drawn)
LBL1  THT-14-423-10  Note: Size: 0.65" x 0.20 "  [Label_650x200]
LOGO1  CAUTION HOT SURFACE  [IEC_HotSurface_Small]  (no BOM)
Logo2  CE Mark  [CE_Mark_5mm]  (no BOM)
Logo3  FCC disclaimer  [FCC_disclaimer]  (no BOM)
Logo4  WEEE logo  [WEEE_Minimum]  (no BOM)
LOGO5  DANGER HIGH VOLTAGE  [IEC_HighVoltage_Small]  (no BOM)
MP1  9774015960R  [FP-9774015960R_ROUND_SPACER_6MM0-MFG]
MP2  9774015960R  [FP-9774015960R_ROUND_SPACER_6MM0-MFG]
MP3  9774015960R  [FP-9774015960R_ROUND_SPACER_6MM0-MFG]
MP4  9774015960R  [FP-9774015960R_ROUND_SPACER_6MM0-MFG]
MP5  9774015960R  [FP-9774015960R_ROUND_SPACER_6MM0-MFG]
MP6  9774015960R  [FP-9774015960R_ROUND_SPACER_6MM0-MFG]
MP7  9774015960R  [FP-9774015960R_ROUND_SPACER_6MM0-MFG]
MP8  9774015960R  [FP-9774015960R_ROUND_SPACER_6MM0-MFG]
MP9  9774015960R  [FP-9774015960R_ROUND_SPACER_6MM0-MFG]
ZZ1  This Assembly Note is for PCB labels only  [AssemblyNoteLabel]  (no BOM)
ZZ2  These assemblies are ESD sensitive, ESD precautions shall be observed.  [AssemblyNote]  (no BOM)
ZZ3  These assemblies must be clean and free from flux and all contaminants. Use of no clean flux is not acceptable.  [AssemblyNote]  (no BOM)
ZZ4  These assemblies must comply with workmanship standards IPC-A-610 Class 2, unless otherwise specified.  [AssemblyNote]  (no BOM)

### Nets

Not connected (* = marked no-connect by the designer): MP1 1*; MP2 1*; MP3 1*; MP4 1*; MP5 1*; MP6 1*; MP7 1*; MP8 1*; MP9 1*

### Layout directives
net class PE: (no net found under the mark)

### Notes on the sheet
- (near FID2) Top
- (near FID5) Bottom
- Variant
- Variant/Label Table
- Label Text
- 001
- N/A

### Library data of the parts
!PCB = CMP-0003618-2: Manufacturer: Any; PartNumber: TIDA-010938 DC-DC
FID1-FID6 = CMP-0077181-1: Fiducial mark.  There is nothing to buy or mount.
LBL1 = CMP-0003625-1: Thermal Transfer Printable Labels, 0.650" W x 0.200" H - 10,000 per roll; Manufacturer: Brady; CompType: Label
LOGO1 = CMP-0074837-1: IEC 61010-1 Hot Surface Warning; SymbolCreator: a0412235; Lib Reference: IEC_HotSurface
Logo2 = CMP-0074844-1: SymbolCreator: a0412235
Logo3 = CMP-0074847-1: FCC_disclaimer; Library Reference: Logo
Logo4 = CMP-0074769-1
LOGO5 = CMP-0074835-1: IEC 61010-1 High Voltage Warning; SymbolCreator: a0412235; Lib Reference: IEC_HighVoltage
MP1-MP9 = CMP-0040203-1: Round Spacer Unthreaded Steel 0.059" (1.50mm); Manufacturer: Wurth Electronics; AEC Qualified: No; Is Female: yes; SizeZ_mm: 1.6mm
ZZ1 = CMP-0003616-3
ZZ2 = CMP-0077236-1
ZZ3 = CMP-0077237-1
ZZ4 = CMP-0077238-1

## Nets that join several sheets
3V3_HVN: TIDA-010938 DCDC_Top (D16.2 J8.1), TIDA-010938 DC-DC_Boost1 (FB1.1), TIDA-010938 DC-DC_Boost2 (FB2.1), TIDA-010938 bidirectional DC-DC_Interleaved1 (C52.1 FB12.1 R22.1 U8.5), TIDA-010938 DC-DC_VoltageMeasurement (C132.2 FB3.1 FB11.1 R12.1), TIDA-010938 DC-DC_Data conditionning (12 pins), TIDA-010938 bidirectional DC-DC_Interleaved2 (C146.1 FB13.1 R47.1 U13.5)
5V_HVN: TIDA-010938 DCDC_Top (D15.2 J6.1), TIDA-010938 bidirectional DC-DC_Interleaved1 (FB9.1), TIDA-010938 bidirectional DC-DC_Interleaved2 (FB10.1)
12V_HVN: TIDA-010938 DCDC_Top (7 pins), TIDA-010938 DC-DC_Boost1 (C5.1 C6.1 U1.44), TIDA-010938 DC-DC_Boost2 (C20.1 U4.44), TIDA-010938 bidirectional DC-DC_Interleaved1 (6 pins), TIDA-010938 bidirectional DC-DC_Interleaved2 (5 pins)
DC_Bus-: TIDA-010938 DCDC_Top (11 pins), TIDA-010938 DC-DC_Boost1 (38 pins), TIDA-010938 DC-DC_Boost2 (37 pins), TIDA-010938 bidirectional DC-DC_Interleaved1 (28 pins), TIDA-010938 DC-DC_Data conditionning (18 pins), TIDA-010938 bidirectional DC-DC_Interleaved2 (27 pins)
GND_BAT: TIDA-010938 DCDC_Top (7 pins), TIDA-010938 bidirectional DC-DC_Interleaved1 (41 pins), TIDA-010938 DC-DC_Data conditionning (18 pins), TIDA-010938 bidirectional DC-DC_Interleaved2 (40 pins)
GND_HVN: TIDA-010938 DCDC_Top (25 pins), TIDA-010938 DC-DC_Boost1 (6 pins), TIDA-010938 DC-DC_Boost2 (6 pins), TIDA-010938 bidirectional DC-DC_Interleaved1 (C49.2 U21.5), TIDA-010938 DC-DC_VoltageMeasurement (19 pins), TIDA-010938 bidirectional DC-DC_Interleaved2 (C57.2 U22.5)
Bat_IN+: TIDA-010938 bidirectional DC-DC_Interleaved1 (C60.2 L9.1), TIDA-010938 bidirectional DC-DC_Interleaved2 (C94.2 L13.6)
Boost1_IN-: TIDA-010938 DC-DC_Boost1 (C9.1 C30.1 R10.1 R17.1), TIDA-010938 DC-DC_VoltageMeasurement (R107.1)
Boost2_IN-: TIDA-010938 DC-DC_Boost2 (C23.1 C224.1 R18.1 R71.1), TIDA-010938 DC-DC_VoltageMeasurement (R111.1)
DC_Bus+: TIDA-010938 DC-DC_Boost1 (7 pins), TIDA-010938 DC-DC_Boost2 (7 pins), TIDA-010938 bidirectional DC-DC_Interleaved1 (19 pins), TIDA-010938 bidirectional DC-DC_Interleaved2 (19 pins)
~{FAULT}_Bat_L1_init: TIDA-010938 bidirectional DC-DC_Interleaved1 (U10.46), TIDA-010938 DC-DC_Data conditionning (R84.1)
~{FAULT}_Bat_L2_init: TIDA-010938 DC-DC_Data conditionning (R76.1), TIDA-010938 bidirectional DC-DC_Interleaved2 (U15.46)
~{FAULT}_Boost1_init: TIDA-010938 DC-DC_Boost1 (U1.46), TIDA-010938 DC-DC_Data conditionning (R75.1)
~{FAULT}_Boost2_init: TIDA-010938 DC-DC_Boost2 (U4.46), TIDA-010938 DC-DC_Data conditionning (R83.1)
~{OC}_Bat_L1_init: TIDA-010938 bidirectional DC-DC_Interleaved1 (U10.48), TIDA-010938 DC-DC_Data conditionning (R89.1)
~{OC}_Bat_L2_init: TIDA-010938 DC-DC_Data conditionning (R78.1), TIDA-010938 bidirectional DC-DC_Interleaved2 (U15.48)
~{OC}_Boost1_init: TIDA-010938 DC-DC_Boost1 (U1.48), TIDA-010938 DC-DC_Data conditionning (R77.1)
~{OC}_Boost2_init: TIDA-010938 DC-DC_Boost2 (U4.48), TIDA-010938 DC-DC_Data conditionning (R85.1)
PV1 Bus+: TIDA-010938 DC-DC_Boost1 (C9.2 L1.5 L1.6 L6.2), TIDA-010938 DC-DC_VoltageMeasurement (R33.1)
PV2 Bus+: TIDA-010938 DC-DC_Boost2 (C23.2 L4.5 L4.6 L8.2), TIDA-010938 DC-DC_VoltageMeasurement (R28.1)
TEMP_Bat_L1_init: TIDA-010938 bidirectional DC-DC_Interleaved1 (U10.49), TIDA-010938 DC-DC_Data conditionning (R117.1)
TEMP_Bat_L2_init: TIDA-010938 DC-DC_Data conditionning (R120.1), TIDA-010938 bidirectional DC-DC_Interleaved2 (U15.49)
TEMP_Boost1_init: TIDA-010938 DC-DC_Boost1 (U1.49), TIDA-010938 DC-DC_Data conditionning (R109.1)
TEMP_Boost2_init: TIDA-010938 DC-DC_Boost2 (U4.49), TIDA-010938 DC-DC_Data conditionning (R112.1)

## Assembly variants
001: not fitted C2 C3 C4 C9 C10 C23 C30 C60 C94 C143 C224 D5 D8 FID1 FID2 FID3 K1 L1 L3 L4 L6 L8 L9 L13 L18 R2 R21 R46 R88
